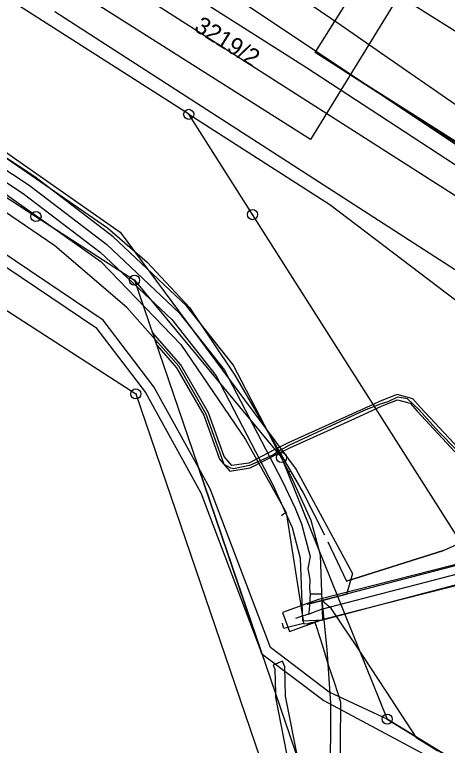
# Model space of a CAD drawing. Extents: x -621168 to -620292, y -1122748 to -1122069.
# Drawn here: x -620574.7 to -620531.9, y -1122599.3 to -1122527.1 of the extents above; entities that cross this region are included whole.
import ezdxf

# ---------------------------------------------------------------- set-up
doc = ezdxf.new("R2010")
doc.units = 0
for name, color, linetype in [('CETIN', 7, 'Continuous'), ('GasNet', 7, 'Continuous'), ('HranDP', 7, 'Continuous'), ('Hranice parcel', 7, 'Continuous'), ('itself', 7, 'Continuous'), ('Parcelní čísla', 7, 'Continuous'), ('PS 06-14-01_trasa_sdělovací_nové', 7, 'Continuous'), ('SEE', 7, 'Continuous'), ('SSZT', 7, 'Continuous'), ('VAS stoka', 7, 'Continuous'), ('VAS vodovod', 7, 'Continuous'), ('Vnitřní kresba', 7, 'Continuous'), ('Vrstva 1', 7, 'Continuous'), ('Vrstva 62', 7, 'Continuous'), ('Věcná břemena k části', 7, 'Continuous'), ('Značky bodu BP', 7, 'Continuous')]:
    doc.layers.add(name, color=color, linetype=linetype)

msp = doc.modelspace()

# ---------------------------------------------------------------- linework, layer by layer
at = {"layer": 'CETIN'}
for points in [[(-620646.43, -1122495.05), (-620612.92, -1122515.84), (-620612.23, -1122516.26), (-620607.1, -1122519.79), (-620583.87, -1122535.51), (-620565.48, -1122548.17), (-620561.56, -1122551.58), (-620557.36, -1122556.05), (-620552.9, -1122562.72), (-620546.13, -1122574.35), (-620544.028, -1122578.529)], [(-620547.37, -1122572.22), (-620547.523, -1122572.289)], [(-620543.69, -1122579.2), (-620541.87, -1122583.1), (-620532.27, -1122580.05), (-620529.5, -1122578.82), (-620525.69, -1122579.49), (-620520.52, -1122580.2), (-620515.66, -1122580.54), (-620511.76, -1122581.44), (-620509.68, -1122582.26), (-620506.2, -1122582.41), (-620494.32, -1122581.82), (-620491.48, -1122581.44), (-620483.44, -1122578.57)], [(-620532.27, -1122580.05), (-620541.87, -1122583.1)]]:
    msp.add_lwpolyline(points, dxfattribs=at)
at = {"layer": 'GasNet'}
for points in [[(-620586.31, -1122535.34), (-620573.22, -1122543.96), (-620565.55, -1122549.81), (-620558.39, -1122556.56), (-620553.9, -1122562.25), (-620551.49, -1122566.93), (-620548.21, -1122573.19), (-620546.94, -1122575.89), (-620546.29, -1122577.44), (-620545.44, -1122580.66), (-620545.67, -1122581.84), (-620545.49, -1122582.92), (-620545.5, -1122583.84), (-620545.45, -1122584.35), (-620545.55, -1122585.95), (-620545.62, -1122586.36)], [(-620545.62, -1122586.36), (-620544.33, -1122585.86), (-620529.1, -1122581.91), (-620527.88, -1122581.68), (-620501.79, -1122593.01), (-620500.52, -1122592.53), (-620484.13, -1122585.56), (-620478.57, -1122583.14), (-620474.2, -1122586.82), (-620449.91, -1122606.86), (-620450.02, -1122607.5), (-620458.5, -1122620.02), (-620458.8, -1122620.62), (-620432.06, -1122640.49), (-620425.64, -1122643.91), (-620417.98, -1122647.99), (-620394.832, -1122667.618)], [(-620545.45, -1122584.35), (-620544.34, -1122584.36), (-620544.31, -1122584.94), (-620543.79, -1122589.85), (-620543.45, -1122595.16)], [(-620545.62, -1122586.36), (-620546.42, -1122586.61), (-620546.89, -1122586.78)], [(-620543.45, -1122595.16), (-620543.47, -1122603.15), (-620543.79, -1122613), (-620544.07, -1122623.3), (-620544.52, -1122634.84), (-620544.92, -1122648.49), (-620545.38, -1122658.87), (-620545.7, -1122668.76), (-620545.98, -1122679.66), (-620545.725, -1122687.651)]]:
    msp.add_lwpolyline(points, dxfattribs=at)
at = {"layer": 'HranDP'}
msp.add_lwpolyline([(-620821.12, -1122358.76), (-620741.46, -1122408.09), (-620679.51, -1122447.56), (-620545.92, -1122532.26), (-620521.41, -1122548.27), (-620511.29, -1122557.64)], dxfattribs=at)
at = {"layer": 'Hranice parcel'}
for points in [[(-620821.12, -1122358.76), (-620741.46, -1122408.09), (-620679.51, -1122447.56), (-620545.92, -1122532.26), (-620521.41, -1122548.27), (-620511.29, -1122557.64)], [(-620821.12, -1122358.76), (-620807.67, -1122367.84), (-620645.72, -1122471.03), (-620587.17, -1122509.18), (-620511.29, -1122557.64)], [(-620557.45, -1122536.96), (-620684.91, -1122455.63), (-620825.92, -1122365.89)], [(-620501.2, -1122595.75), (-620510.22, -1122594.3), (-620521.17, -1122592.53), (-620528.72, -1122582.15), (-620536.04, -1122570.64), (-620547.19, -1122553.1), (-620551.15, -1122546.87), (-620557.45, -1122536.96)], [(-620557.45, -1122536.96), (-620543.5, -1122545.86), (-620527.5, -1122558.02), (-620519.77, -1122564.93), (-620511.02, -1122574.99), (-620502.74, -1122587.44), (-620502.51, -1122588.68), (-620501.2, -1122595.75)], [(-620576.58, -1122544.45), (-620572.54, -1122547.06), (-620562.8, -1122553.35)], [(-620581.67, -1122552.32), (-620562.67, -1122564.59), (-620546.5, -1122612)], [(-620562.8, -1122553.35), (-620548.28, -1122570.88), (-620537.83, -1122596.73), (-620531.96, -1122600.32), (-620510.44, -1122604.21)], [(-620562.8, -1122553.35), (-620534.95, -1122635.03), (-620510.44, -1122604.21)]]:
    msp.add_lwpolyline(points, dxfattribs=at)
at = {"layer": 'itself'}
msp.add_lwpolyline([(-620530.966, -1122570.132), (-620532.766, -1122568.302), (-620534.705, -1122566.112), (-620535.816, -1122565.082), (-620536.826, -1122564.912), (-620537.766, -1122565.362), (-620538.416, -1122565.552), (-620540.126, -1122566.232), (-620547.566, -1122569.682), (-620548.366, -1122570.132), (-620549.136, -1122570.642), (-620551.436, -1122571.662), (-620553.016, -1122571.982), (-620553.026, -1122571.982), (-620553.296, -1122571.942), (-620553.946, -1122571.562), (-620554.176, -1122570.902), (-620555.716, -1122566.582), (-620558.436, -1122561.862), (-620563.546, -1122556.052), (-620570.666, -1122549.952), (-620584.476, -1122540.562)], dxfattribs=at)
at = {"layer": 'PS 06-14-01_trasa_sdělovací_nové'}
msp.add_lwpolyline([(-620377.179, -1122637.257), (-620411.557, -1122614.916), (-620456.111, -1122587.123), (-620544.953, -1122530.859), (-620538.89, -1122521.208), (-620538.89, -1122521.208)], dxfattribs=at)
at = {"layer": 'SEE'}
msp.add_lwpolyline([(-620377.188, -1122637.273), (-620390.254, -1122629.02), (-620411.934, -1122614.961), (-620423.125, -1122608.012), (-620468.337, -1122579.91), (-620468.337, -1122579.91), (-620460.94, -1122568.103), (-620517.418, -1122533.032), (-620535.001, -1122522.477), (-620545.407, -1122539.454), (-620611.375, -1122497.696), (-620665.569, -1122462.755), (-620686.035, -1122449.829), (-620727.537, -1122423.183), (-620794.508, -1122379.862), (-620815.52, -1122356.954), (-620832.168, -1122344.663), (-620847.808, -1122332.592), (-620908.257, -1122294.686)], dxfattribs=at)
at = {"layer": 'SSZT'}
msp.add_lwpolyline([(-620879.238, -1122313.316), (-620842.993, -1122336.61), (-620835.049, -1122343.251), (-620812.66, -1122358.949), (-620764.902, -1122389.752), (-620688.594, -1122438.969), (-620596.981, -1122496.725), (-620576.744, -1122509.484), (-620506.746, -1122556.123), (-620447.293, -1122593.619), (-620377.761, -1122638.259)], dxfattribs=at)
at = {"layer": 'VAS stoka'}
for points in [[(-620781.72, -1122408.87), (-620776.69, -1122412.14), (-620774.2, -1122412.02), (-620772.21, -1122412.95), (-620766.77, -1122415.95), (-620758.11, -1122421.89), (-620737.16, -1122435.39), (-620726.71, -1122442.22), (-620705.9, -1122455.54), (-620681.71, -1122471.08), (-620665.23, -1122481.83), (-620655.606, -1122488.117), (-620638.12, -1122499.53), (-620609.99, -1122517.38), (-620585.88, -1122533.44), (-620564.23, -1122548.6), (-620546.83, -1122572.05), (-620541.253, -1122582.331), (-620541.865, -1122584.423), (-620543.527, -1122584.845), (-620544.25, -1122585.029)], [(-620544.25, -1122585.029), (-620545.68, -1122585.41), (-620545.7, -1122585.34), (-620544.74, -1122585.09), (-620529.09, -1122581.01), (-620528.27, -1122580.72), (-620501.26, -1122592.08), (-620484.32, -1122584.76), (-620478.68, -1122582.19), (-620475.52, -1122584.33), (-620473.62, -1122582.33), (-620454.46, -1122552.49), (-620449.28, -1122555.81), (-620438.79, -1122557.25), (-620438.13, -1122557.28)], [(-620532.839, -1122599.89), (-620534.923, -1122598.593), (-620537.947, -1122593.969), (-620540.971, -1122589.345), (-620542.157, -1122587.591), (-620543.343, -1122585.837), (-620543.797, -1122585.433), (-620544.25, -1122585.029)]]:
    msp.add_lwpolyline(points, dxfattribs=at)
at = {"layer": 'VAS vodovod'}
for points in [[(-620783.05, -1122410.36), (-620779.49, -1122412.44), (-620776.82, -1122413.57), (-620766.15, -1122419), (-620759.23, -1122423.16), (-620738.05, -1122436.88), (-620666.7, -1122483.31), (-620630.69, -1122506.76), (-620611.44, -1122519.95), (-620587.32, -1122536.52), (-620566.14, -1122551.51), (-620558.22, -1122559.71), (-620551.85, -1122569.08), (-620547.83, -1122576.32), (-620546.15, -1122586.98), (-620546.105, -1122587.264)], [(-620548.28, -1122576.61), (-620548.08, -1122576.43), (-620547.83, -1122576.32)], [(-620544.967, -1122587.097), (-620544.863, -1122587.05), (-620544.76, -1122587.004), (-620544.537, -1122586.974), (-620544.315, -1122586.943), (-620527.61, -1122582.527), (-620502.02, -1122594.032), (-620500.778, -1122593.455), (-620500.104, -1122593.231), (-620483.666, -1122586.375), (-620481.327, -1122585.405), (-620479.583, -1122584.864), (-620478.408, -1122584.641), (-620477.754, -1122585.105), (-620476.869, -1122585.61)], [(-620546.105, -1122587.264), (-620547.819, -1122587.714), (-620548.065, -1122587.764), (-620548.143, -1122587.449), (-620548.194, -1122587.245)], [(-620546.105, -1122587.264), (-620545.745, -1122587.294), (-620545.542, -1122587.242), (-620545.338, -1122587.191), (-620545.152, -1122587.144), (-620544.967, -1122587.097)], [(-620544.967, -1122587.097), (-620544.948, -1122587.248), (-620544.929, -1122587.398), (-620544.87, -1122587.521), (-620544.812, -1122587.644), (-620544.235, -1122589.495), (-620543.658, -1122591.345), (-620543.047, -1122593.188), (-620542.435, -1122595.031), (-620542.492, -1122599.187), (-620542.549, -1122603.343), (-620542.689, -1122608.247), (-620542.829, -1122613.151), (-620542.948, -1122618.376), (-620543.067, -1122623.6), (-620543.31, -1122629.222), (-620543.553, -1122634.844), (-620543.681, -1122641.775)]]:
    msp.add_lwpolyline(points, dxfattribs=at)
at = {"layer": 'Vnitřní kresba'}
msp.add_line((-620504.94, -1122569.2), (-620570.69, -1122526.84), dxfattribs=at)
at = {"layer": 'Vrstva 1'}
msp.add_line((-620544.953, -1122530.859), (-620538.89, -1122521.208), dxfattribs=at)
for points in [[(-620575.439, -1122500.82), (-620568.605, -1122505.122), (-620561.797, -1122509.415), (-620554.878, -1122513.77), (-620548.817, -1122517.58), (-620545.736, -1122519.521), (-620540.158, -1122523.031), (-620536.763, -1122525.164), (-620530.044, -1122529.401), (-620522.74, -1122533.999), (-620516.175, -1122538.134), (-620510.877, -1122541.462), (-620509.772, -1122542.153), (-620508.122, -1122543.191), (-620500.939, -1122547.694), (-620490.94, -1122553.975)], [(-620575.439, -1122500.82), (-620568.605, -1122505.122), (-620561.797, -1122509.415), (-620554.878, -1122513.77), (-620548.817, -1122517.58), (-620545.736, -1122519.521), (-620540.158, -1122523.031), (-620536.763, -1122525.164), (-620530.044, -1122529.401), (-620522.74, -1122533.999), (-620516.175, -1122538.134), (-620510.877, -1122541.462), (-620509.772, -1122542.153), (-620508.122, -1122543.191), (-620500.939, -1122547.694), (-620490.94, -1122553.975)], [(-620582.331, -1122501.971), (-620566.971, -1122511.728), (-620560.029, -1122516.238), (-620551.869, -1122521.685), (-620548.619, -1122523.887), (-620542.396, -1122528.151), (-620538.064, -1122531.158), (-620531.122, -1122535.952), (-620524.966, -1122540.177), (-620518.618, -1122544.427), (-620513.645, -1122547.697), (-620506.55, -1122552.247), (-620496.304, -1122558.659), (-620480.231, -1122568.734), (-620462.233, -1122580.043), (-620447.551, -1122589.267), (-620431.6, -1122599.485), (-620414.27, -1122610.379), (-620398.172, -1122620.479), (-620378.269, -1122633.015), (-620375.666, -1122634.655)], [(-620456.111, -1122587.123), (-620500.015, -1122559.595), (-620522.22, -1122545.451), (-620544.953, -1122530.859)]]:
    msp.add_lwpolyline(points, dxfattribs=at)
at = {"layer": 'Vrstva 62'}
for p, q in [((-620542.011, -1122527.533), (-620542.011, -1122527.533)), ((-620542.781, -1122528.769), (-620542.781, -1122528.769)), ((-620537.663, -1122530.553), (-620537.663, -1122530.553)), ((-620538.465, -1122531.763), (-620538.465, -1122531.763))]:
    msp.add_line(p, q, dxfattribs=at)
at = {"layer": 'Věcná břemena k části'}
for points in [[(-620662.49, -1122492.8), (-620663.99, -1122495.13), (-620660.86, -1122494.48), (-620566.61, -1122558.04), (-620561.72, -1122564.46), (-620556.24, -1122574.37), (-620550.21, -1122590.27), (-620556.49, -1122571.86), (-620560.88, -1122563.9), (-620565.91, -1122557.3), (-620661.78, -1122492.65)], [(-620547.49, -1122588.06), (-620544.04, -1122586.82), (-620527.96, -1122582.73), (-620501.79, -1122594.1), (-620501.53, -1122593.99), (-620501.92, -1122591.86), (-620527.8, -1122580.63), (-620544.62, -1122584.9), (-620548.17, -1122586.18)]]:
    msp.add_lwpolyline(points, close=True, dxfattribs=at)
for points in [[(-620586.86, -1122536.18), (-620573.8, -1122544.78), (-620566.2, -1122550.57), (-620559.13, -1122557.24), (-620554.74, -1122562.8), (-620549.11, -1122573.63), (-620547.24, -1122577.78), (-620546.44, -1122580.81), (-620546.21, -1122587), (-620544.21, -1122586.92), (-620544.44, -1122580.51), (-620545.34, -1122577.1), (-620547.31, -1122572.75), (-620553.06, -1122561.7), (-620557.65, -1122555.88), (-620564.9, -1122549.05), (-620572.64, -1122543.14), (-620585.76, -1122534.5)], [(-620530.8, -1122569.94), (-620534.53, -1122565.94), (-620535.3, -1122565.07), (-620536.85, -1122564.65), (-620538.52, -1122565.32), (-620539.22, -1122565.64), (-620541.91, -1122566.85), (-620547.68, -1122569.45), (-620548.93, -1122570.09), (-620551.52, -1122571.42), (-620553.2, -1122571.67), (-620553.96, -1122570.77), (-620555.49, -1122566.47), (-620558.24, -1122561.71), (-620561.03, -1122558.53), (-620560.61, -1122559.77), (-620558.64, -1122562.01), (-620555.95, -1122566.69), (-620554.4, -1122571.03), (-620553.4, -1122572.21), (-620551.36, -1122571.9), (-620548.6, -1122570.49), (-620547.46, -1122569.91), (-620541.41, -1122567.17), (-620538.95, -1122566.06), (-620538.32, -1122565.78), (-620536.81, -1122565.17), (-620535.58, -1122565.51), (-620534.89, -1122566.28), (-620531.14, -1122570.32)], [(-620534.53, -1122643.11), (-620533.24, -1122636.48), (-620531.35, -1122632.09), (-620527.61, -1122626.14), (-620510.87, -1122608.51), (-620509.33, -1122605.27), (-620511, -1122604.91), (-620531.96, -1122600.32), (-620537.83, -1122596.73), (-620543.57, -1122594.05), (-620549.38, -1122589.64), (-620555.33, -1122573.96), (-620556.49, -1122571.86), (-620550.21, -1122590.27), (-620544.11, -1122594.89), (-620531.56, -1122601.62), (-620511.69, -1122605.79), (-620511.71, -1122607.93), (-620522.17, -1122618.96), (-620528.4, -1122625.53), (-620532.24, -1122631.63), (-620534.2, -1122636.18), (-620535.53, -1122643.03)], [(-620546.64, -1122600.75), (-620547.87, -1122594.46), (-620547.94, -1122591.57), (-620548.19, -1122591), (-620549.11, -1122591.4), (-620548.94, -1122591.79), (-620548.88, -1122594.18), (-620548.87, -1122594.56), (-620545.3, -1122612.77)]]:
    msp.add_lwpolyline(points, dxfattribs=at)
at = {"layer": 'Značky bodu BP'}
for centre, radius in [((-620557.45, -1122536.96), 0.5), ((-620557.45, -1122536.96), 0.0303), ((-620551.15, -1122546.87), 0.5), ((-620572.54, -1122547.06), 0.5), ((-620572.54, -1122547.06), 0.0303), ((-620551.15, -1122546.87), 0.0303), ((-620562.8, -1122553.35), 0.5), ((-620562.8, -1122553.35), 0.0303), ((-620562.67, -1122564.59), 0.5), ((-620562.67, -1122564.59), 0.0303), ((-620548.28, -1122570.88), 0.5), ((-620548.28, -1122570.88), 0.0303), ((-620537.83, -1122596.73), 0.5), ((-620537.83, -1122596.73), 0.0303)]:
    msp.add_circle(centre, radius, dxfattribs=at)

# ---------------------------------------------------------------- texts
at = {"layer": 'Parcelní čísla'}
msp.add_text('3219/2', height=1.7, rotation=328, dxfattribs=at).set_placement((-620557.014, -1122528.619))

doc.saveas('drawing.dxf')
